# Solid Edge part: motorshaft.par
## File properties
Author: Robert a Rhodes jr
Template: NORMENG.PAR
Last saved by: Cadcim
Revision: 4
Application: Solid Edge
Accuracy: 0.99
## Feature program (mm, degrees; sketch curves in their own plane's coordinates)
sketch for "unnamed Protrusion 1" plane through (0, 0, 0) normal (0, -1, 0) x-axis (1, 0, 0)
  circle centre (0, 0) radius 18.415
extrude "unnamed Protrusion 1" add finite 609.6 along -normal
sketch for "unnamed RevolvedCutout 1" plane through (0, 0, 0) normal (0, 0, 1) x-axis (1, 0, 0)
  line (18.415, 592.328) -> (18.415, 596.9)
  line (18.415, 596.9) -> (14.1403, 596.9)
  line (14.1403, 596.9) -> (14.1403, 592.328)
  line (14.1403, 592.328) -> (18.415, 592.328)
revolve "unnamed RevolvedCutout 1" cut finite 360 deg about sketch line (-1.0997, 601.5888) -> (-1.0997, 629.75)
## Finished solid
Body 1: solid body, 7 faces, 6 edges, 0 vertices.
  Faces by surface: plane 4, cylinder 3
  Edges by curve: circle 6
Bounding box of the edges (mm): 36.830 x 609.600 x 36.830, from (-18.415, 0, -18.415) to (18.415, 609.6, 18.415).
Cylindrical faces by radius (mm): R15.24 x1, R18.415 x2
Planar faces by outward normal: +y 2, -y 2
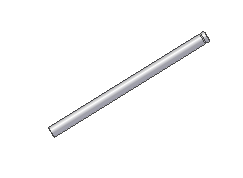
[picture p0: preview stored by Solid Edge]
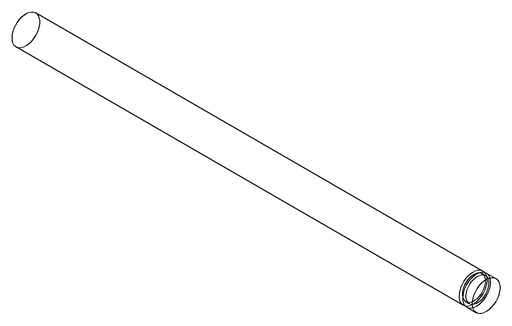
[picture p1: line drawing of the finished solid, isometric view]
